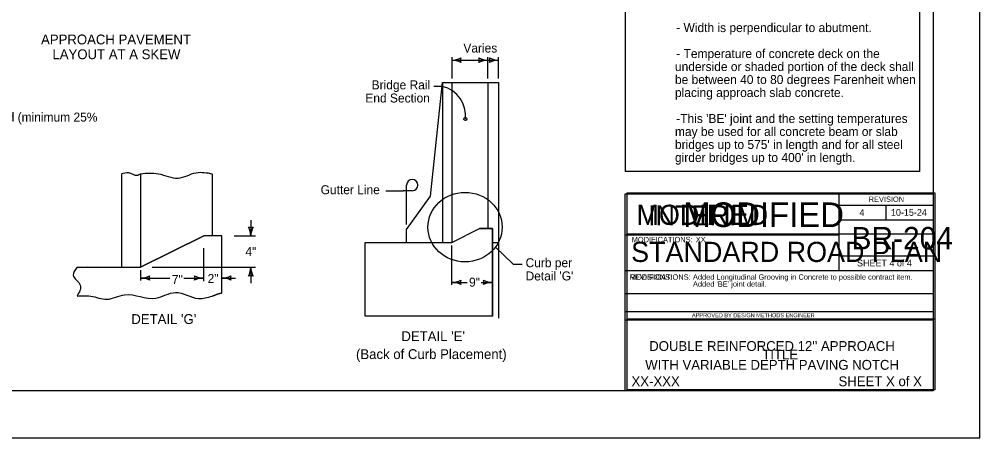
# Model space of a CAD drawing. Extents: x -2135039 to -2120895, y -2139150 to -2136566.
# Drawn here: x -2123042 to -2120895, y -2139150 to -2138216 of the extents above; entities that cross this region are included whole.
import ezdxf

# ---------------------------------------------------------------- set-up
doc = ezdxf.new("R2010")
doc.units = 0
for name, color, linetype in [('dsnCellElements', 7, 'Continuous'), ('dsnDOTLogo', 7, 'Continuous'), ('dsnNonPlotable', 7, 'Continuous'), ('dsnStdBlock', 7, 'Continuous'), ('dsnstdblockInterim', 7, 'Continuous'), ('dsnStdLabel', 7, 'Continuous'), ('dsnStdLogo', 7, 'Continuous'), ('dsnstdModifiedBlock', 7, 'Continuous'), ('Level 1', 7, 'Continuous'), ('Level 2', 7, 'Continuous'), ('Level 3', 7, 'Continuous')]:
    doc.layers.add(name, color=color, linetype=linetype)

msp = doc.modelspace()

# ---------------------------------------------------------------- linework, layer by layer
at = {"layer": 'dsnCellElements'}
for p, q in [((-2122176.3, -2138606.2), (-2122176.3, -2138586.2)), ((-2122163.8, -2138598.7), (-2122183.8, -2138598.7))]:
    msp.add_line(p, q, dxfattribs=at)
msp.add_circle((-2122044.9, -2138438.7), 3.54, dxfattribs=at)
msp.add_arc((-2122163.8, -2138586.2), 12.5, 270, 180, dxfattribs=at)
at = {"layer": 'dsnDOTLogo'}
msp.add_lwpolyline([(-2124239, -2139150.4), (-2120895, -2139150.4), (-2120895, -2136566.4), (-2124239, -2136566.4)], close=True, dxfattribs=at)
at = {"layer": 'dsnNonPlotable'}
for p, q in [((-2121687.5, -2137085.9), (-2121687.5, -2138555.9)), ((-2121029.5, -2137085.9), (-2121029.5, -2138555.9)), ((-2121029.5, -2138555.9), (-2121687.5, -2138555.9))]:
    msp.add_line(p, q, dxfattribs=at)
at = {"layer": 'dsnStdLabel'}
for centre, radius, start, end in [((-2122075, -2138264.9), 42.5, 270, 298.0725), ((-2122075, -2138349.9), 42.5, 61.9275, 90), ((-2122039.4, -2138307.4), 16.4, 162.2666, 197.7334), ((-2122030.4, -2138307.4), 16.4, 342.2666, 17.7333), ((-2121994.7, -2138264.9), 42.5, 241.9275, 270), ((-2121994.7, -2138349.9), 42.5, 90, 118.0725), ((-2122006.4, -2138307.4), 16.4, 342.2666, 17.7333), ((-2121970.8, -2138264.9), 42.5, 241.9275, 270), ((-2121970.8, -2138349.9), 42.5, 90, 118.0725), ((-2122524.7, -2138664.2), 16.4, 252.2666, 287.7333), ((-2122567.2, -2138699.9), 42.5, 360, 28.0725), ((-2122482.2, -2138699.9), 42.5, 151.9275, 180), ((-2122567.2, -2138769.8), 42.5, 331.9275, 360), ((-2122482.2, -2138769.8), 42.5, 180, 208.0725), ((-2122771.2, -2138751.2), 42.5, 270, 298.0725), ((-2122735.6, -2138793.7), 16.4, 162.2666, 197.7334), ((-2122665.8, -2138793.7), 16.4, 342.2666, 17.7333), ((-2122630.2, -2138751.2), 42.5, 241.9275, 270), ((-2122589.2, -2138751.2), 42.5, 270, 298.0725), ((-2122553.6, -2138793.7), 16.4, 162.2666, 197.7334), ((-2122524.7, -2138805.4), 16.4, 72.2666, 107.7334), ((-2122771.2, -2138836.2), 42.5, 61.9275, 90), ((-2122630.2, -2138836.2), 42.5, 90, 118.0725), ((-2122589.2, -2138836.2), 42.5, 61.9275, 90), ((-2122075, -2138760.9), 42.5, 270, 298.0725), ((-2122075, -2138845.9), 42.5, 61.9275, 90), ((-2122039.4, -2138803.4), 16.4, 162.2666, 197.7334), ((-2122019.9, -2138803.4), 16.4, 342.2666, 17.7333), ((-2121984.3, -2138760.9), 42.5, 241.9275, 270), ((-2121984.3, -2138845.9), 42.5, 90, 118.0725)]:
    msp.add_arc(centre, radius, start, end, dxfattribs=at)
at = {"layer": 'dsnStdLogo'}
for p, q in [((-2121210.4, -2138605.9), (-2121210.4, -2138697.3)), ((-2121210.4, -2138630.9), (-2120999.5, -2138630.9)), ((-2121104.9, -2138630.9), (-2121104.9, -2138664.1)), ((-2121210.4, -2138664.1), (-2120999.5, -2138664.1)), ((-2121687.5, -2138697.3), (-2121210.4, -2138697.3)), ((-2121210.4, -2138697.3), (-2121210.4, -2138777.3)), ((-2120999.5, -2138745.1), (-2121210.4, -2138745.1)), ((-2121687.5, -2138777.3), (-2120999.5, -2138777.3)), ((-2121687.5, -2138828.3), (-2120999.5, -2138828.3)), ((-2121687.5, -2138868.3), (-2120999.5, -2138868.3)), ((-2121687.5, -2138887.3), (-2120999.5, -2138887.3))]:
    msp.add_line(p, q, dxfattribs=at)
msp.add_lwpolyline([(-2121687.5, -2138605.9), (-2120999.5, -2138605.9), (-2120999.5, -2139045.9), (-2121687.5, -2139045.9)], close=True, dxfattribs=at)
at = {"layer": 'dsnstdModifiedBlock'}
for p, q in [((-2121683.2, -2138695), (-2120995.1, -2138695)), ((-2121683.2, -2138885), (-2120995.1, -2138885))]:
    msp.add_line(p, q, dxfattribs=at)
msp.add_lwpolyline([(-2121683.2, -2138603.7), (-2120995.1, -2138603.7), (-2120995.1, -2139043.7), (-2121683.2, -2139043.7)], close=True, dxfattribs=at)
at = {"layer": 'Level 1'}
msp.add_lwpolyline([(-2124134.5, -2137035.9), (-2120999.5, -2137035.9), (-2120999.5, -2139045.9), (-2124134.5, -2139045.9)], close=True, dxfattribs=at)
at = {"layer": 'Level 2'}
for p, q in [((-2122075, -2138307.4), (-2122045.9, -2138307.4)), ((-2122074.7, -2138348), (-2122074.7, -2138300.7)), ((-2122074.7, -2138307.4), (-2121994.7, -2138307.4)), ((-2121999.1, -2138307.4), (-2121970.8, -2138307.4)), ((-2121994.7, -2138348), (-2121994.7, -2138300.7)), ((-2121970.8, -2138348), (-2121970.8, -2138300.7)), ((-2122123, -2138611.1), (-2122096.3, -2138357.1)), ((-2122096.3, -2138357.1), (-2121995, -2138357.1)), ((-2122096.3, -2138357.1), (-2122096.3, -2138714.7)), ((-2122075, -2138357.1), (-2122075, -2138714.7)), ((-2121995, -2138357.1), (-2121995, -2138683.1)), ((-2121995, -2138357.1), (-2121970.8, -2138357.1)), ((-2121970.8, -2138357.1), (-2121970.8, -2138883.5)), ((-2122096, -2138366.3), (-2122115.5, -2138366.3)), ((-2122813.9, -2138560.8), (-2122813.9, -2138769.8)), ((-2122771.2, -2138560.8), (-2122771.2, -2138769.8)), ((-2122611.2, -2138560.8), (-2122611.2, -2138699.9)), ((-2122222.7, -2138598.7), (-2122183.8, -2138598.7)), ((-2122176.3, -2138674), (-2122176.3, -2138606.2)), ((-2122176.3, -2138685.7), (-2122123, -2138611.1)), ((-2122611.2, -2138643.4), (-2122611.2, -2138699.9)), ((-2121995, -2138651.5), (-2121995, -2138683.1)), ((-2122524.7, -2138664.2), (-2122524.7, -2138699.9)), ((-2121984.7, -2138683.1), (-2122013.7, -2138683.1)), ((-2122013.7, -2138683.1), (-2121984.7, -2138683.1)), ((-2121984.7, -2138878.9), (-2121984.7, -2138683.1)), ((-2121984.7, -2138683.1), (-2121984.7, -2138878.9)), ((-2122589.3, -2138699.9), (-2122630, -2138699.9)), ((-2122589.3, -2138827.1), (-2122589.3, -2138699.9)), ((-2122561.8, -2138699.9), (-2122514, -2138699.9)), ((-2122176.3, -2138714.7), (-2122176.3, -2138685.7)), ((-2122630.2, -2138727.2), (-2122630.2, -2138801.1)), ((-2122075, -2138808.6), (-2122075, -2138721.2)), ((-2121984.7, -2138714.7), (-2121970.8, -2138714.7)), ((-2121978, -2138725.1), (-2121938, -2138762.7)), ((-2122889, -2138769.8), (-2122913.4, -2138769.9)), ((-2122772.4, -2138769.8), (-2122913.4, -2138769.9)), ((-2122913.2, -2138769.8), (-2122867.2, -2138769.9)), ((-2122867.2, -2138769.9), (-2122889, -2138769.8)), ((-2122771.3, -2138769.8), (-2122867.2, -2138769.9)), ((-2122867.2, -2138769.9), (-2122771.3, -2138769.8)), ((-2122771.2, -2138769.8), (-2122772.4, -2138769.8)), ((-2122745.4, -2138769.8), (-2122514, -2138769.8)), ((-2122524.7, -2138769.8), (-2122524.7, -2138805.5)), ((-2121938, -2138762.7), (-2121918.2, -2138762.7)), ((-2122771.3, -2138776.2), (-2122771.3, -2138799.1)), ((-2122771.2, -2138793.7), (-2122706, -2138793.7)), ((-2122674.2, -2138793.7), (-2122630.2, -2138793.7)), ((-2122589.2, -2138793.7), (-2122558.8, -2138793.7)), ((-2122075, -2138803.4), (-2122041.3, -2138803.4)), ((-2122009.8, -2138803.4), (-2121984.3, -2138803.4))]:
    msp.add_line(p, q, dxfattribs=at)
for points in [[(-2122075, -2138714.7), (-2122013.7, -2138683.1)], [(-2122075, -2138714.7), (-2122013.7, -2138683.1)], [(-2122630, -2138699.9), (-2122771.2, -2138769.8), (-2122771.3, -2138769.8)], [(-2122771.3, -2138769.8), (-2122630, -2138699.9)], [(-2122589.3, -2138699.9), (-2122611.2, -2138699.9), (-2122630, -2138699.9)], [(-2122589.3, -2138827.1), (-2122589.3, -2138827.1), (-2122589.3, -2138699.9)], [(-2121984.7, -2138878.9), (-2122269.1, -2138878.9), (-2122269.1, -2138714.7), (-2122123, -2138714.7), (-2122075, -2138714.7)], [(-2121984.7, -2138878.9), (-2122269.1, -2138878.9), (-2122269.1, -2138714.7), (-2122123, -2138714.7), (-2122075, -2138714.7)]]:
    msp.add_lwpolyline(points, dxfattribs=at)
msp.add_arc((-2122111.2, -2138431.2), 66.7, 353.5756, 76.8823, dxfattribs=at)
msp.add_ellipse((-2122045.7, -2138680.1), major_axis=(83, 0), ratio=0.93542, dxfattribs=at)
for points in [[(-2122813.9, -2138560.8), (-2122798.2, -2138558.3), (-2122779.2, -2138564.2), (-2122771.2, -2138560.8)], [(-2122771.2, -2138560.8), (-2122731.2, -2138560.8), (-2122687.4, -2138570.8), (-2122646.6, -2138558.6), (-2122611.2, -2138560.8)], [(-2122913.4, -2138769.9), (-2122921.7, -2138787.4), (-2122905.9, -2138809.6), (-2122913.2, -2138834.1)], [(-2122913.4, -2138769.9), (-2122921.7, -2138787.4), (-2122905.9, -2138809.6), (-2122913.2, -2138834.1)], [(-2122913.2, -2138834.1), (-2122882.6, -2138834.1), (-2122846.5, -2138841.1), (-2122806.8, -2138831.2), (-2122736.8, -2138838.8), (-2122693.1, -2138825.9), (-2122641.7, -2138839.4), (-2122611.2, -2138834.1)], [(-2122913.2, -2138834.1), (-2122882.6, -2138834.1), (-2122846.5, -2138841.1), (-2122806.8, -2138831.2), (-2122736.8, -2138838.8), (-2122693.1, -2138825.9), (-2122641.7, -2138839.4), (-2122611.2, -2138834.1)], [(-2122611.2, -2138834.1), (-2122597.1, -2138829), (-2122591.9, -2138827.5)]]:
    msp.add_spline(points, degree=3, dxfattribs=at)
msp.add_open_spline([(-2122611.2, -2138834.1), (-2122610.3, -2138833.8), (-2122609.4, -2138833.6), (-2122608.5, -2138833.2), (-2122607.6, -2138832.9), (-2122606.6, -2138832.6), (-2122605.7, -2138832.2), (-2122603.9, -2138831.5), (-2122602.1, -2138830.8), (-2122600.2, -2138830.1), (-2122598.4, -2138829.4), (-2122596.6, -2138828.8), (-2122594.7, -2138828.2), (-2122593.8, -2138827.9), (-2122592.9, -2138827.7), (-2122592, -2138827.5), (-2122591.5, -2138827.5), (-2122591.1, -2138827.4), (-2122590.6, -2138827.3), (-2122590.2, -2138827.2), (-2122589.7, -2138827.2), (-2122589.3, -2138827.1)], degree=3, dxfattribs=at)

# ---------------------------------------------------------------- texts
at = {"layer": 'dsnNonPlotable'}
msp.add_text('REVISIONS:', height=12, dxfattribs=at).set_placement((-2121677.5, -2138797.6))
at = {"layer": 'dsnStdBlock'}
for s, height, p in [('MODIFIED', 45, (-2121662.4, -2138675.1)), ('MODIFICATIONS:', 12, (-2121677.5, -2138797.6))]:
    msp.add_text(s, height=height, dxfattribs=at).set_placement(p)
at = {"layer": 'dsnstdblockInterim'}
msp.add_text('INTERIM', height=45, dxfattribs=at).set_placement((-2121636.5, -2138676.3))
at = {"layer": 'dsnStdLogo'}
for s, height, p in [('REVISION', 12, (-2121143.4, -2138623.8)), ('4', 15, (-2121164.1, -2138655.3)), ('10-15-24', 15, (-2121093.6, -2138654.8)), ('BR-204', 50, (-2121181.7, -2138729.8)), ('STANDARD ROAD PLAN', 45.001, (-2121674.4, -2138757.9)), ('SHEET 4 of 4', 15, (-2121169.4, -2138767.9)), ('Added Longitudinal Grooving in Concrete to possible contract item. ', 12, (-2121536.2, -2138797.5)), ("Added 'BE' joint detail.", 12, (-2121536.2, -2138813.1)), ('APPROVED BY DESIGN METHODS ENGINEER', 9.003, (-2121538.5, -2138881.4)), ("DOUBLE REINFORCED 12'' APPROACH", 22, (-2121634, -2138956.6)), ('WITH VARIABLE DEPTH PAVING NOTCH', 22, (-2121642.9, -2138998.6))]:
    msp.add_text(s, height=height, dxfattribs=at).set_placement(p)
at = {"layer": 'dsnstdModifiedBlock'}
for s, height, p in [('MODIFIED', 55, (-2121558.1, -2138679.9)), ('MODIFICATIONS:', 12, (-2121673.2, -2138713.9)), ('XX', 12, (-2121529.9, -2138713.9)), ('TITLE', 22, (-2121381.1, -2138975.4)), ('XX-XXX', 22, (-2121673.6, -2139035.3)), ('SHEET X of X', 22, (-2121210.8, -2139035.3))]:
    msp.add_text(s, height=height, dxfattribs=at).set_placement(p)
at = {"layer": 'Level 1'}
for s, p in [('         - Width is perpendicular to abutment.', (-2121640.4, -2138244.6)), ('         - Temperature of concrete deck on the ', (-2121640.4, -2138302.6)), ('underside or shaded portion of the deck shall ', (-2121576.4, -2138331.6)), ('be between 40 to 80 degrees Farenheit when ', (-2121576.4, -2138360.6)), ('placing approach slab concrete.', (-2121576.4, -2138389.6)), ("         -This 'BE' joint and the setting temperatures ", (-2121640.4, -2138447.6)), ('may be used for all concrete beam or slab ', (-2121576.4, -2138476.6)), ("bridges up to 575' in length and for all steel ", (-2121576.4, -2138505.6)), ("girder bridges up to 400' in length.", (-2121576.4, -2138534.6))]:
    msp.add_text(s, height=20, dxfattribs=at).set_placement(p)
at = {"layer": 'Level 2'}
for s, height, p in [('APPROACH PAVEMENT', 22, (-2122993.6, -2138272.1)), ('Varies', 20, (-2122049.5, -2138290.2)), ('LAYOUT AT A SKEW', 22, (-2122968.1, -2138305.1)), ('Bridge Rail ', 20, (-2122254.5, -2138372.4)), ('End Section', 20, (-2122268.6, -2138401.8)), ('Gutter Line', 20, (-2122368.5, -2138606.6)), ('4"', 20, (-2122536.8, -2138744.8)), ('Curb per', 20, (-2121910.4, -2138769.6)), ('7"', 20, (-2122701.1, -2138806.8)), ('2"', 20, (-2122621.2, -2138804.7)), ("Detail 'G'", 20, (-2121910.4, -2138799.1)), ('9"', 20, (-2122036.7, -2138813)), ("DETAIL 'G'", 22, (-2122791.8, -2138896.4)), ("DETAIL 'E'", 22, (-2122188, -2138934.7))]:
    msp.add_text(s, height=height, dxfattribs=at).set_placement(p)
at = {"layer": 'Level 3'}
for s, height, p in [('Closed Cell Backer Rod (minimum 25%', 20, (-2123337.2, -2138444.4)), ('(Back of Curb Placement)', 22, (-2122289.5, -2138974.7))]:
    msp.add_text(s, height=height, dxfattribs=at).set_placement(p)

doc.saveas('drawing.dxf')
